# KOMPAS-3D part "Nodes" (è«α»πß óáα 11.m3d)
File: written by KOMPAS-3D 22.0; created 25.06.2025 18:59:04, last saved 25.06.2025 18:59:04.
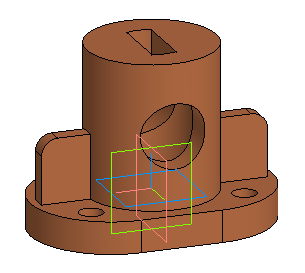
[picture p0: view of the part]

Document properties: Автор: Helen; Полное имя файла: D:\MY\WORK\MPEI\ППЭ_2025-2026\Варианты\Вар 11 СБ\Корпус вар 11.m3d

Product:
- Part/product: Nodes

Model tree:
1. Операция без истории:1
